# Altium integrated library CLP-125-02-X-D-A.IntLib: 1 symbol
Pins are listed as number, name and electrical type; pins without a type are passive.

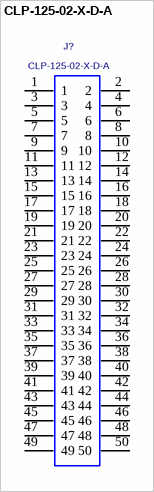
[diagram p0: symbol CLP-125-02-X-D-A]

## CLP-125-02-X-D-A
designator J?
LOW PROFILE SOCKET STRIP, .505: (1.27mm) PITCH, 50 PINS, ALIGNMENT PINS; MANUFACTURER: SAMTEC
footprint CLP-125-02-X-D-A
pins: 1, 2, 3, 4, 5, 6, 7, 8, 9, 10, 11, 12, 13, 14, 15, 16, 17, 18, 19, 20, 21, 22, 23, 24, 25, 26, 27, 28, 29, 30, 31, 32, 33, 34, 35, 36, 37, 38, 39, 40, 41, 42, 43, 44, 45, 46, 47, 48, 49, 50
